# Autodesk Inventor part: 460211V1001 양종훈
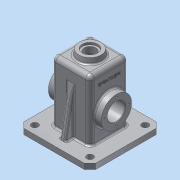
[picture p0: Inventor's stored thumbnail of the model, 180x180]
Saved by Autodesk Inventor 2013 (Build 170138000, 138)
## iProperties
Created: 2016-02
Part Number: 460211V1001 양종훈
Material: 알루미늄 6061
Document SubType Name: Modeling
Designer: dgall
Density: 2.71 g/cm^3
Mass: 940.602 g
Surface Area: 1042.24 cm^2
Volume: 347.086 cm^3
Author: dgall
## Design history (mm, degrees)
sketch "스케치4"
  geometry: L1 (35, 35)-(-35, 35); L2 (-35, 35)-(-35, -35); L3 (-35, -35)-(35, -35); L4 (35, -35)-(35, 35); 1 further point
  constraints: 8 end point, 2 parallel, 1 horizontal, 1 perpendicular
  dimensions: "d32" = 70 distance between parallel lines of L4 L2; "d34" = 70 distance between parallel lines of L3 L1; "d35" = 35 distance from line of L2 point (0, 0) (= 0.5 x d32); "d36" = 35 distance from line of point (0, 0) L3 (= 0.5 x d34)
extrude "돌출4" new body sketch "스케치4" distance "d37" = 120; taper "d38" = 0 deg
feature "쉘1" dims "d39" = 5
sketch "스케치5"
  geometry: L1 (-35, 35)-(35, 35) reference; L2 (-35, -35)-(-35, 35) reference; L3 (35, -35)-(-35, -35) reference; L4 (35, 35)-(35, -35) reference; L5 (65, 65)-(-65, 65); L6 (-65, 65)-(-65, -65); L7 (-65, -65)-(65, -65); L8 (65, -65)-(65, 65); 1 further point
  constraints: 8 end point, 2 parallel, 1 horizontal, 1 perpendicular
  dimensions: "d40" = 130 distance between parallel lines of L8 L6; "d42" = 130 distance between parallel lines of L7 L5; "d43" = 65 distance from line of point (0, 0) L6 (= 0.5 x d40); "d44" = 65 distance from line of point (0, 0) L5 (= 0.5 x d42)
extrude "돌출5" join sketch "스케치5" distance "d45" = 10; taper "d46" = 0 deg
chamfer "모따기2" distance "d47" = 10; stored, may be unused: second distance "d48" = 2, angle "d49" = 45 deg
sketch "스케치6"
  geometry: L1 (65, -55)-(65, 55) reference; L2 (55, 65)-(-55, 65) reference; L3 (-55, -65)-(55, -65) reference; C1 r 6 at (50, 50); C2 r 6 at (50, -50); C3 r 6 at (-50, 50); C4 r 6 at (-50, -50); 1 further point
  constraints: 4 centre point, 1 horizontal, 1 vertical, 6 other
  dimensions: "d50" = 15 distance from line of C1.centre L2; "d51" = 15 distance from line of C1.centre L1; "d52" = 12 diameter of C1; "d55" = 100 distance of C1.centre C2.centre; "d58" = 100 distance of C1.centre C3.centre
extrude "돌출6" cut sketch "스케치6" distance "d61" = 10; taper "d62" = 0 deg
sketch "스케치7"
  geometry: L1 (-35, 10)-(-35, 120) reference; L2 (35, 120)-(-35, 120) reference; L3 (35, 10)-(35, 120) reference; L4 (55, 10)-(-55, 10) reference; L5 (55, 10)-(65, 10) reference; L6 (65, 10)-(65, 0) reference; L7 (65, 0)-(55, 0) reference; L8 (56, 0)-(44, 0) reference; L9 (-55, 0)-(55, 0) reference; L10 (-55, 0)-(-65, 0) reference; L11 (-65, 0)-(-65, 10) reference; L12 (-65, 10)-(-55, 10) reference; L13 (-48, 55)-(48, 55); L14 (-48, 55)-(-48, 82.5); L15 (-48, 82.5)-(-35, 82.5); L16 (-30, 82.5)-(-23, 75.5); L17 (-23, 75.5)-(-23, 55); L18 (-30, 0)-(-30, 115) reference; L19 (30, 0)-(30, 115) reference; L20 (30, 82.5)-(23, 75.5); L21 (23, 75.5)-(23, 55); L22 (48, 55)-(48, 82.5); L23 (48, 82.5)-(35, 82.5); L24 (-35, 82.5)-(-30, 82.5); L25 (35.5, 82.5)-(30, 82.5); 1 further point
  constraints: 22 end point, 6 point on line, 5 perpendicular, 2 parallel, 1 collinear
  dimensions: "d63" = 55 distance from line of point (0, 0) L13; "d64" = 96 distance of L13.start L13.end; "d65" = 48 horizontal distance of L13.start point (0, 0) (= 0.5 x d64); "d66" = 55 diameter of L15 L13; "d67" = 135 deg angle of L16 L17; "d68" = 7 distance from line of L17.end L18; "d69" = 55 diameter of L16.start L13; "d70" = 0 distance from line of L16.start L18; "d71" = 135 deg angle of L21 L20; "d72" = 55 diameter of L20.start L13; "d73" = 7 distance between parallel lines of L21 L19; "d74" = 55 diameter of L23 L13
revolve "회전1" sketch "스케치7" stored, may be unused: angle "d78" = 90 deg
sketch "스케치8"
  geometry: C1 r 27.5 at (0, 0) reference; C2 r 16 at (0, 0); 1 further point
  constraints: 1 centre point, 1 coincident
  dimensions: "d79" = 32 diameter of C2
extrude "돌출7" cut sketch "스케치8" stored distance "d81" = 0; taper "d82" = 0 deg
fillet "모깎기1" dims "d83" = 0.5
fillet "모깎기2" dims "d84" = 3
fillet "모깎기3" dims "d85" = 3
chamfer "모따기3" distance "d86" = 1; stored, may be unused: second distance "d87" = 2, angle "d88" = 45 deg
sketch "스케치9" dims "d89" = 45
  geometry: C1 r 27.5 at (0, 0) reference; C2 r 17 at (0, 0) reference; 6 further points
  constraints: 2 vertical alignment, 1 coincident, 7 other
  dimensions: "d93" = 360 deg dimension on point (0, 0) point (0, 22.5) (derived)
hole "구멍1" sketch "스케치9" at (0, 22.5), (-22.5, 0), (0, -22.5), (22.5, 0) diameter "d95" = 3.242; stored, may be unused: countersink angle "d99" = 90 deg, drill point angle "d101" = 118 deg; dims "d96" = 8, "d97" = 4, "d98" = 2, "d100" = 10
sketch "스케치10"
  geometry: L1 (-65, 0)-(-65, 10) reference; L2 (-55, 0)-(-65, 0) reference; L3 (-44, 0)-(-56, 0) reference; L4 (-55, 0)-(55, 0) reference; L5 (-65, 10)-(-55, 10) reference; L6 (-56, 10)-(-44, 10) reference; L7 (55, 10)-(-55, 10) reference; L8 (-35, 10)-(-35, 120) reference; L9 (35, 10)-(35, 120) reference; L10 (55, 10)-(65, 10) reference; L11 (-35, 95.069)-(-50, 10); 1 further point
  constraints: 2 end point, 2 point on line
  dimensions: "d103" = 10 deg angle of L1 L11; "d104" = 15 distance from line of L11.end L1
feature "리브1" sketch "스케치10" dims "d105" = 1, "d106" = 10, "d107" = 0, "d108" = 0, "d109" = 1, "d110" = 1
fillet "모깎기4" dims "d111" = 8
fillet "모깎기5" dims "d112" = 3
fillet "모깎기6" dims "d113" = 3
fillet "모깎기7" dims "d114" = 3
sketch "스케치11"
  geometry: L1 (-27, 120)-(27, 120) reference; L2 (65, 10)-(65, 0) reference; L3 (-65, 0)-(-65, 10) reference; L4 (0, 0)-(0, 130); L5 (27, 0)-(-27, 0) reference; L6 (0, 130)-(20, 130); L7 (20, 130)-(21.763, 120); L8 (35, 112)-(35, 13) reference; L9 (21.763, 120)-(0, 120)
  constraints: 8 end point, 2 point on line, 1 midpoint, 1 parallel, 1 perpendicular
  dimensions: "d115" = 130 distance of L4.end L4.start; "d116" = 10 deg angle of L7 L8; "d117" = 40 diameter of L6.end L4
revolve "회전2" sketch "스케치11" stored, may be unused: angle "d118" = 90 deg
sketch "스케치12"
  geometry: C1 r 20 at (0, 0) reference; C2 r 14 at (0, 0)
  constraints: 1 centre point, 1 coincident
  dimensions: "d119" = 28 diameter of C2
extrude "돌출8" cut sketch "스케치12" distance "d121" = 4; taper "d122" = 0 deg
sketch "스케치13"
  geometry: C1 r 21.763 at (0, 0) reference; C2 r 10.5 at (0, 0)
  constraints: 1 centre point, 1 coincident
  dimensions: "d123" = 21 diameter of C2
extrude "돌출9" cut sketch "스케치13" stored distance "d125" = 0; taper "d126" = 0 deg
sketch "스케치14"
  geometry: L1 (6.775, 6.261)-(6.775, 47.739); L2 (6.775, 47.739)-(17.225, 47.739); L3 (17.225, 47.739)-(17.225, 6.261); L4 (17.225, 6.261)-(6.775, 6.261); L5 (12, 6.261)-(12, 47.739); L6 (6.775, 27)-(17.225, 27); L7 (0, -8)-(99, -8) reference; L8 (-18, 7)-(-18, 47) reference; 1 further point
  constraints: 4 end point, 4 midpoint, 2 other
  dimensions: "d127" = 35 distance between parallel lines of L6 L7; "d128" = 30 distance between parallel lines of L5 L8
feature "엠보싱1" sketch "스케치14" dims "d32" = 70, "d34" = 70, "d35" = 35 (= 0.5 x d32), "d36" = 35 (= 0.5 x d34), "d129" = 0.5, "d130" = 0
fillet "모깎기8" dims "d131" = 3
node "솔리드2"
mirror "대칭1"
mirror "대칭2"
mirror "대칭3"
other parameters: "d75" = 32
